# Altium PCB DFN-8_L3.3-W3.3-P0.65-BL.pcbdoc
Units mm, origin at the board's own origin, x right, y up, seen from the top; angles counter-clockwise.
Board outline 16 x 16.7 mm, 2 copper layers (Top Layer, Bottom Layer), stack 0.07 mm thick; 1 components, 0 nets, 5 pads, 0 vias.
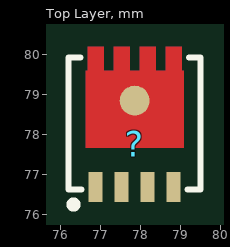
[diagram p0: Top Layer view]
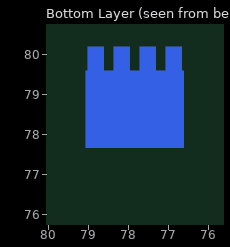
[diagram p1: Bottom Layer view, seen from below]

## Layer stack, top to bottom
Top Solder Mask Layer: solder mask 0.01, Dk 3.3
Top Layer: signal copper 0.035
Bottom Layer: signal copper 0.035
Bottom Solder Mask Layer: solder mask 0.01, Dk 3.3

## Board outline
85.851,69.85 69.85,69.85 69.85,86.549 85.851,86.549

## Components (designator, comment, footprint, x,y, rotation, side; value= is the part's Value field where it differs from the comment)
? "DFN-8_L3.3-W3.3-P0.65-BL" DFN-8_L3.3-W3.3-P0.65-BL 77.85,77.469 r0 top

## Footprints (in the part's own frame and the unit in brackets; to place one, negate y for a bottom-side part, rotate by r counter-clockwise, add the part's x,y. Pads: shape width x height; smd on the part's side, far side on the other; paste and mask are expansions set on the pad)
DFN-8_L3.3-W3.3-P0.65-BL [mm]
  rect 0.35x0.75 smd paste+0 mask+0.05: 1(-0.975,-0.779) 2(-0.325,-0.779) 3(0.325,-0.779) 4(0.975,-0.779)
  round 0.75 smd: 5(0.002,1.38)
  Top Layer region: -1.222,0.201 -1.222,2.129 -1.174,2.129 -1.174,2.73 -0.773,2.73 -0.773,2.129 -0.524,2.129 -0.524,2.73 -0.123,2.73 -0.123,2.129 0.126,2.129 0.126,2.73 0.528,2.73 0.528,2.129 0.777,2.129 0.777,2.73 0.777,2.129 0.777,2.73 1.178,2.73 1.178,2.129 1.226,2.129 1.226,0.201
  Bottom Layer region: -1.222,0.201 -1.222,2.129 -1.174,2.129 -1.174,2.73 -0.773,2.73 -0.773,2.129 -0.524,2.129 -0.524,2.73 -0.123,2.73 -0.123,2.129 0.126,2.129 0.126,2.73 0.528,2.73 0.528,2.129 0.777,2.129 0.777,2.73 0.777,2.129 0.777,2.73 1.178,2.73 1.178,2.129 1.226,2.129 1.226,0.201
  Multi-Layer region: -1.222,0.201 -1.222,2.129 -1.174,2.129 -1.174,2.73 -0.773,2.73 -0.773,2.129 -0.524,2.129 -0.524,2.73 -0.123,2.73 -0.123,2.129 0.126,2.129 0.126,2.73 0.528,2.73 0.528,2.129 0.777,2.129 0.777,2.73 0.777,2.129 0.777,2.73 1.178,2.73 1.178,2.129 1.226,2.129 1.226,0.201
  silkscreen extent -1.65,-1.27 1.65,2.46

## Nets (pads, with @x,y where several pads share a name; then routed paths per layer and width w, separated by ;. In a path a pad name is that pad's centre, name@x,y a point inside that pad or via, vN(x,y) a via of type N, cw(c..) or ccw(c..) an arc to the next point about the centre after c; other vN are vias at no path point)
pads on no net: ?.1 ?.2 ?.3 ?.4 ?.5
